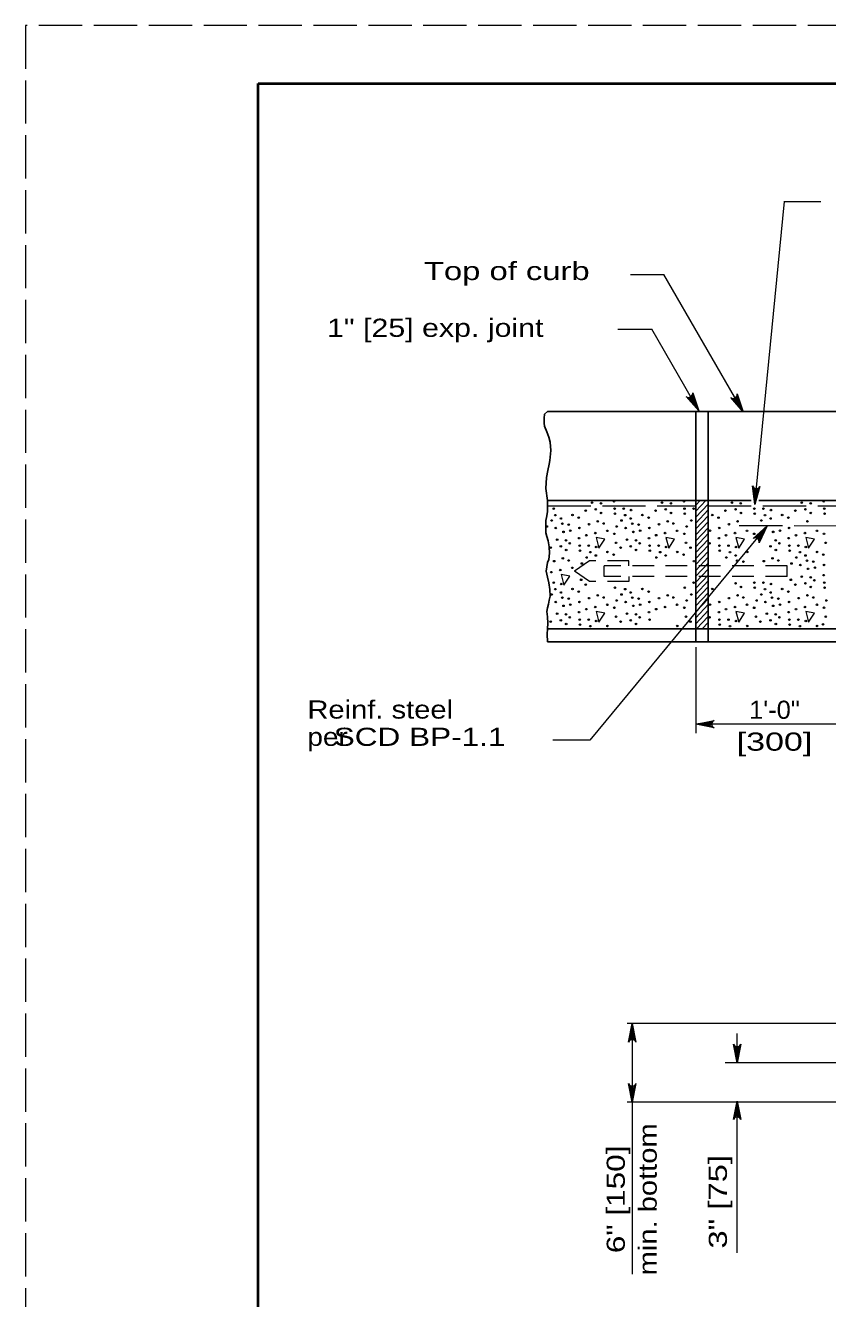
# Model space of a CAD drawing. Extents: x 1352.5 to 1386.5, y 735.9 to 779.9.
# Drawn here: x 1352.51 to 1359.41, y 768.97 to 779.92 of the extents above; entities that cross this region are included whole.
import ezdxf
from ezdxf.enums import TextEntityAlignment as Align

# ---------------------------------------------------------------- set-up
doc = ezdxf.new("R2010")
doc.units = 0
doc.header["$LTSCALE"] = 0.062
doc.linetypes.add('LONG_DASHED', pattern=[7.5, 6, -1.5])
doc.linetypes.add('MEDIUM_DASHED', pattern=[4.5, 3, -1.5])
doc.layers.add('1', color=7, linetype='Continuous', lineweight=13)

msp = doc.modelspace()

# ---------------------------------------------------------------- linework, layer by layer
at = {"layer": '1', "lineweight": 25}
for p, q in [((1354.513, 779.41967), (1386.013, 779.41967)), ((1356.99975, 776.599), (1369.78625, 776.599)), ((1358.27417, 776.599), (1358.27417, 774.62017)), ((1358.27417, 775.83442), (1356.99975, 775.83442)), ((1358.75225, 775.83442), (1358.38042, 775.83442)), ((1360.12208, 775.83442), (1358.818, 775.83442)), ((1358.38042, 774.62017), (1359.56983, 774.62017))]:
    msp.add_line(p, q, dxfattribs=at)
at = {"layer": '1'}
for p, q in [((1358.78142, 775.8), (1359.03875, 778.406)), ((1359.03108, 778.40683), (1359.34958, 778.40683)), ((1357.71275, 777.779), (1358.00133, 777.779)), ((1358.68267, 776.59883), (1358.00133, 777.779)), ((1357.60417, 777.307), (1357.89592, 777.307)), ((1358.30017, 776.60675), (1357.89592, 777.307)), ((1358.21083, 776.72175), (1358.30017, 776.60675)), ((1358.22192, 776.7225), (1358.30017, 776.60675)), ((1358.2315, 776.72625), (1358.30017, 776.60675)), ((1358.24142, 776.735), (1358.30017, 776.60675)), ((1358.24675, 776.74442), (1358.30017, 776.60675)), ((1358.59267, 776.71333), (1358.68267, 776.59883)), ((1358.60375, 776.71417), (1358.68267, 776.59883)), ((1358.61333, 776.718), (1358.68267, 776.59883)), ((1358.62317, 776.72675), (1358.68267, 776.59883)), ((1358.6285, 776.73617), (1358.68267, 776.59883)), ((1358.773, 775.94542), (1358.78142, 775.8)), ((1358.81542, 775.94367), (1358.78142, 775.8)), ((1358.7825, 775.93975), (1358.78142, 775.8)), ((1358.80567, 775.93892), (1358.78142, 775.8)), ((1358.79258, 775.93742), (1358.78142, 775.8)), ((1358.27417, 775.74275), (1358.36075, 775.83442)), ((1358.27417, 775.79367), (1358.31267, 775.83442)), ((1358.38042, 775.83442), (1358.27417, 775.83442)), ((1358.27417, 775.69192), (1358.38042, 775.80442)), ((1358.27417, 775.641), (1358.38042, 775.7535)), ((1358.27417, 775.59017), (1358.38042, 775.70258)), ((1358.27417, 775.53925), (1358.38042, 775.65167)), ((1358.27417, 775.48833), (1358.38042, 775.60083)), ((1358.7835, 775.5135), (1358.8895, 775.61617)), ((1358.79425, 775.51225), (1358.8895, 775.61617)), ((1358.80608, 775.50642), (1358.8895, 775.61617)), ((1358.81333, 775.49908), (1358.8895, 775.61617)), ((1358.81833, 775.48917), (1358.8895, 775.61617)), ((1358.27408, 775.43742), (1358.38042, 775.55)), ((1358.27417, 775.38658), (1358.38042, 775.49908)), ((1358.27417, 775.33575), (1358.38042, 775.44817)), ((1358.27417, 775.28483), (1358.38042, 775.39725)), ((1358.27417, 775.234), (1358.38042, 775.34642)), ((1358.27417, 775.18308), (1358.38042, 775.29558)), ((1358.27417, 775.13217), (1358.38042, 775.24467)), ((1358.27417, 775.08125), (1358.38042, 775.19383)), ((1358.27417, 775.0305), (1358.38042, 775.14292)), ((1358.27417, 774.97958), (1358.38042, 775.092)), ((1358.27417, 774.92867), (1358.38042, 775.04108)), ((1358.27417, 774.87775), (1358.38042, 774.99025)), ((1358.27417, 774.82692), (1358.38042, 774.93942)), ((1358.27417, 774.776), (1358.38042, 774.8885)), ((1358.28117, 774.73258), (1358.38042, 774.83758)), ((1358.32925, 774.73258), (1358.38042, 774.78667)), ((1358.37725, 774.73258), (1358.38042, 774.73583)), ((1358.27417, 774.57517), (1358.27417, 773.8335)), ((1358.41842, 773.93233), (1358.27417, 773.91217)), ((1358.4135, 773.92233), (1358.27417, 773.91217)), ((1358.412, 773.91217), (1358.27417, 773.91217)), ((1358.41458, 773.89917), (1358.27417, 773.91217)), ((1358.42008, 773.88983), (1358.27417, 773.91217)), ((1359.56983, 773.91217), (1358.27417, 773.91217)), ((1359.52733, 771.33708), (1357.68633, 771.33708)), ((1357.70658, 771.19108), (1357.72883, 771.33708)), ((1357.71592, 771.19667), (1357.72883, 771.33708)), ((1357.72883, 771.19917), (1357.72883, 771.33708)), ((1357.73908, 771.19767), (1357.72883, 771.33708)), ((1357.749, 771.19283), (1357.72883, 771.33708)), ((1357.72883, 771.33708), (1357.72883, 769.18275)), ((1358.63025, 771.00042), (1358.63025, 771.25167)), ((1358.61, 771.14467), (1358.63025, 771.00042)), ((1358.62, 771.13975), (1358.63025, 771.00042)), ((1358.6525, 771.14633), (1358.63025, 771.00042)), ((1358.64317, 771.14083), (1358.63025, 771.00042)), ((1358.63025, 771.13825), (1358.63025, 771.00042)), ((1363.12942, 771.00042), (1358.52633, 771.00042)), ((1357.70867, 770.80667), (1357.72883, 770.66242)), ((1357.71867, 770.80175), (1357.72883, 770.66242)), ((1357.75117, 770.80833), (1357.72883, 770.66242)), ((1357.74183, 770.80283), (1357.72883, 770.66242)), ((1357.72883, 770.80025), (1357.72883, 770.66242)), ((1359.52733, 770.66242), (1357.68633, 770.66242)), ((1358.60792, 770.52533), (1358.63025, 770.67125)), ((1358.61725, 770.53083), (1358.63025, 770.67125)), ((1358.63025, 770.53342), (1358.63025, 770.67125)), ((1358.64042, 770.53192), (1358.63025, 770.67125)), ((1358.65042, 770.527), (1358.63025, 770.67125)), ((1358.63025, 769.36675), (1358.63025, 770.67125))]:
    msp.add_line(p, q, dxfattribs=at)
at = {"layer": '1', "linetype": 'LONG_DASHED'}
for p, q in [((1356.99975, 775.7895), (1358.27417, 775.7895)), ((1358.38042, 775.7895), (1360.12208, 775.7895)), ((1358.64892, 775.61933), (1359.90083, 775.61817))]:
    msp.add_line(p, q, dxfattribs=at)
at = {"layer": '1', "linetype": 'MEDIUM_DASHED'}
for p, q in [((1357.48833, 775.18233), (1357.48833, 775.27225)), ((1359.06008, 775.27225), (1357.48833, 775.27225)), ((1359.06008, 775.18233), (1359.06008, 775.27225)), ((1357.36083, 775.13733), (1357.23217, 775.22733)), ((1357.70067, 775.13733), (1357.36083, 775.13733)), ((1359.06008, 775.18233), (1357.48833, 775.18233)), ((1357.70067, 775.18233), (1357.70067, 775.13733))]:
    msp.add_line(p, q, dxfattribs=at)
at = {"layer": '1', "linetype": 'LONG_DASHED'}
msp.add_lwpolyline([(1352.513, 757.91967), (1386.513, 757.91967), (1386.513, 779.91967), (1352.513, 779.91967)], close=True, dxfattribs=at)
at = {"layer": '1', "lineweight": 25}
for points in [[(1386.013, 758.41967), (1354.513, 758.41967), (1354.513, 779.41967)], [(1356.99975, 776.599), (1356.97533, 776.57875), (1356.97292, 776.54342), (1356.9705, 776.50042), (1356.97533, 776.47517), (1356.99442, 776.42467), (1357.01108, 776.37925), (1357.02308, 776.33625), (1357.02783, 776.26558), (1357.02067, 776.17967), (1357.01583, 776.14683), (1357.00392, 776.09383), (1356.99208, 776.03325), (1356.98725, 775.93725), (1356.99975, 775.83442)], [(1358.38042, 776.599), (1358.38042, 774.73258), (1358.38042, 774.62017)], [(1356.99975, 775.83442), (1356.99975, 775.7895), (1357.00158, 775.73767), (1356.99208, 775.68975), (1356.98725, 775.662), (1356.98725, 775.62917), (1356.98483, 775.58867), (1356.98483, 775.55583), (1356.99442, 775.52558), (1357.00633, 775.48767), (1357.01583, 775.43717), (1357.01825, 775.38167), (1357.01108, 775.32858), (1357.00158, 775.30075), (1356.98967, 775.2275), (1356.99925, 775.177), (1357.01108, 775.1265), (1357.02067, 775.07092), (1357.02308, 775.01283), (1357.01583, 774.9775), (1357.00867, 774.94467), (1356.99925, 774.91183), (1356.99442, 774.8815), (1357.00158, 774.83608), (1357.00392, 774.7805), (1356.99975, 774.73258), (1358.38042, 774.73258), (1359.56983, 774.73258)], [(1356.99975, 774.73258), (1356.99683, 774.6845), (1356.99975, 774.62017)], [(1358.38042, 774.62017), (1358.27417, 774.62017), (1356.99975, 774.62017)]]:
    msp.add_lwpolyline(points, dxfattribs=at)
at = {"layer": '1', "lineweight": 40}
msp.add_lwpolyline([(1354.513, 779.41967), (1386.013, 779.41967), (1386.013, 758.41967), (1354.513, 758.41967)], close=True, dxfattribs=at)
msp.add_lwpolyline([(1354.513, 779.41967), (1386.013, 779.41967), (1386.013, 758.41967), (1354.513, 758.41967)], close=True, dxfattribs=at)
at = {"layer": '1'}
for points in [[(1358.24842, 776.76075), (1358.30017, 776.60675), (1358.19317, 776.729)], [(1358.63, 776.75258), (1358.68267, 776.59883), (1358.575, 776.7205)], [(1358.82608, 775.95625), (1358.78142, 775.8), (1358.7625, 775.96142)], [(1358.8895, 775.61617), (1357.36375, 773.77533), (1357.04583, 773.77533)], [(1358.76775, 775.50858), (1358.8895, 775.61617), (1358.8185, 775.47008)], [(1358.4335, 773.88025), (1358.27417, 773.91217), (1358.4335, 773.944)], [(1357.697, 771.17775), (1357.72883, 771.33708), (1357.76075, 771.17775)], [(1358.66208, 771.15975), (1358.63025, 771.00042), (1358.59833, 771.15975)], [(1357.76075, 770.82175), (1357.72883, 770.66242), (1357.697, 770.82175)], [(1358.59833, 770.51192), (1358.63025, 770.67125), (1358.66208, 770.51192)]]:
    msp.add_lwpolyline(points, dxfattribs=at)
at = {"layer": '1', "lineweight": 25}
msp.add_lwpolyline([(1358.38042, 774.73258), (1358.38042, 775.83442), (1358.27417, 775.83442), (1358.27417, 774.73258)], close=True, dxfattribs=at)
at = {"layer": '1'}
for points in [[(1357.41808, 775.51725), (1357.44225, 775.425), (1357.49175, 775.50283)], [(1358.01883, 775.51725), (1358.04308, 775.425), (1358.0925, 775.50283)], [(1358.6195, 775.51725), (1358.64383, 775.425), (1358.69333, 775.50283)], [(1359.22025, 775.51725), (1359.24458, 775.425), (1359.29408, 775.50283)], [(1357.11767, 775.19917), (1357.14192, 775.107), (1357.19133, 775.18483)], [(1357.41808, 774.88117), (1357.44225, 774.789), (1357.49175, 774.86683)], [(1358.6195, 774.88117), (1358.64383, 774.789), (1358.69333, 774.86683)], [(1359.22025, 774.88117), (1359.24458, 774.789), (1359.29408, 774.86683)]]:
    msp.add_lwpolyline(points, close=True, dxfattribs=at)
at = {"layer": '1', "linetype": 'MEDIUM_DASHED'}
msp.add_lwpolyline([(1357.70067, 775.27225), (1357.70067, 775.31725), (1357.36083, 775.31725), (1357.23217, 775.22733)], dxfattribs=at)
at = {"layer": '1'}
for centre, start, end in [((1358.21434, 776.75603), 231.97282, 7.79895), ((1358.596, 776.74763), 232.30117, 8.1273), ((1358.7953, 775.97165), 197.46542, 333.29155), ((1358.78537, 775.47907), 344.86022, 120.68634), ((1358.44634, 773.91218), 112.08782, 247.91395), ((1357.72889, 771.16488), 22.08782, 157.91395), ((1358.63017, 771.17258), 202.08782, 337.91395), ((1357.72882, 770.83459), 202.08782, 337.91395), ((1358.63024, 770.49906), 22.08782, 157.91395)]:
    msp.add_arc(centre, 0.03438, start, end, dxfattribs=at)
for centre in [(1357.38373, 775.81688), (1357.46028, 775.81026), (1357.57247, 775.82886), (1357.98449, 775.81688), (1358.06104, 775.81026), (1358.17323, 775.82886), (1358.58525, 775.81688), (1358.6618, 775.81026), (1359.18601, 775.81688), (1359.26255, 775.81026), (1359.37475, 775.82886), (1357.05447, 775.76531), (1357.06744, 775.70865), (1357.11525, 775.6803), (1357.21502, 775.71035), (1357.26854, 775.68803), (1357.32862, 775.74814), (1357.41537, 775.75932), (1357.46108, 775.7281), (1357.57733, 775.76531), (1357.57973, 775.72153), (1357.65523, 775.76531), (1357.66819, 775.70865), (1357.716, 775.6803), (1357.71926, 775.75243), (1357.81578, 775.71035), (1357.8693, 775.68803), (1357.92937, 775.74814), (1358.01613, 775.75932), (1358.06184, 775.7281), (1358.17809, 775.76531), (1358.18049, 775.72153), (1358.25599, 775.76531), (1358.41654, 775.71035), (1358.47006, 775.68803), (1358.53013, 775.74814), (1358.61689, 775.75932), (1358.6626, 775.7281), (1358.77884, 775.76531), (1358.78125, 775.72153), (1358.85674, 775.76531), (1358.86971, 775.70865), (1358.91752, 775.6803), (1358.92077, 775.75243), (1359.0173, 775.71035), (1359.07081, 775.68803), (1359.13089, 775.74814), (1359.21765, 775.75932), (1359.26336, 775.7281), (1359.3796, 775.76531), (1359.38201, 775.72153), (1356.99494, 775.61134), (1357.03575, 775.66312), (1357.07144, 775.59788), (1357.12826, 775.63567), (1357.13792, 775.56523), (1357.18258, 775.62788), (1357.19635, 775.57556), (1357.27505, 775.59867), (1357.35805, 775.63111), (1357.4327, 775.65512), (1357.48216, 775.6371), (1357.51375, 775.5744), (1357.5957, 775.61134), (1357.6365, 775.66312), (1357.6722, 775.59788), (1357.72902, 775.63567), (1357.73868, 775.56523), (1357.78334, 775.62788), (1357.79711, 775.57556), (1357.87581, 775.59867), (1357.95881, 775.63111), (1358.03345, 775.65512), (1358.08292, 775.6371), (1358.11451, 775.5744), (1358.19646, 775.61134), (1358.23726, 775.66312), (1358.39786, 775.57556), (1358.47656, 775.59867), (1358.55957, 775.63111), (1358.63421, 775.65512), (1358.71526, 775.5744), (1358.83802, 775.66312), (1358.9402, 775.56523), (1358.99862, 775.57556), (1359.07732, 775.59867), (1359.23497, 775.65512), (1359.31602, 775.5744), (1357.08336, 775.49887), (1357.1599, 775.49224), (1357.19179, 775.46707), (1357.27209, 775.51085), (1357.27695, 775.4473), (1357.33367, 775.53661), (1357.35485, 775.4473), (1357.41077, 775.55463), (1357.57543, 775.54864), (1357.59004, 775.47136), (1357.68411, 775.49887), (1357.76066, 775.49224), (1357.79255, 775.46707), (1357.87285, 775.51085), (1357.87771, 775.4473), (1357.93443, 775.53661), (1357.95561, 775.4473), (1358.01153, 775.55463), (1358.17618, 775.54864), (1358.1908, 775.47136), (1358.39331, 775.46707), (1358.47361, 775.51085), (1358.47847, 775.4473), (1358.53519, 775.53661), (1358.55636, 775.4473), (1358.61228, 775.55463), (1358.77694, 775.54864), (1358.96218, 775.49224), (1358.99407, 775.46707), (1359.07437, 775.51085), (1359.07922, 775.4473), (1359.13595, 775.53661), (1359.15712, 775.4473), (1359.21304, 775.55463), (1359.3777, 775.54864), (1359.39232, 775.47136), (1357.02824, 775.43012), (1357.115, 775.44131), (1357.13232, 775.33711), (1357.1607, 775.41009), (1357.27935, 775.40352), (1357.33612, 775.34511), (1357.36781, 775.39064), (1357.41562, 775.36228), (1357.41888, 775.43442), (1357.5154, 775.39233), (1357.56892, 775.37002), (1357.62899, 775.43012), (1357.71575, 775.44131), (1357.76146, 775.41009), (1357.88011, 775.40352), (1357.93688, 775.34511), (1357.96857, 775.39064), (1358.01638, 775.36228), (1358.01964, 775.43442), (1358.11616, 775.39233), (1358.16968, 775.37002), (1358.22975, 775.43012), (1358.48087, 775.40352), (1358.53764, 775.34511), (1358.56933, 775.39064), (1358.61714, 775.36228), (1358.62039, 775.43442), (1358.71692, 775.39233), (1358.91727, 775.44131), (1358.93459, 775.33711), (1358.96298, 775.41009), (1359.08163, 775.40352), (1359.1384, 775.34511), (1359.17009, 775.39064), (1359.2179, 775.36228), (1359.22115, 775.43442), (1359.31767, 775.39233), (1359.37119, 775.37002), (1357.05767, 775.3131), (1357.11039, 775.23661), (1357.18178, 775.31908), (1357.21337, 775.25638), (1357.29532, 775.29333), (1358.25919, 775.3131), (1358.63016, 775.31765), (1358.68448, 775.30986), (1358.85995, 775.3131), (1358.98405, 775.31908), (1359.0976, 775.29333), (1359.17409, 775.27986), (1359.23091, 775.31765), (1359.24058, 775.24721), (1359.28523, 775.30986), (1359.299, 775.25755), (1359.3777, 775.28066), (1357.03329, 775.21859), (1357.05447, 775.12928), (1357.28967, 775.15335), (1358.25599, 775.12928), (1358.61689, 775.12329), (1358.77884, 775.12928), (1358.85674, 775.12928), (1359.09194, 775.15335), (1359.18601, 775.18085), (1359.21765, 775.12329), (1359.26255, 775.17423), (1359.29445, 775.14905), (1359.37475, 775.19283), (1359.3796, 775.12928), (1357.03575, 775.02709), (1357.06744, 775.07262), (1357.11525, 775.04427), (1357.1185, 775.1164), (1357.21502, 775.07432), (1357.26854, 775.05201), (1357.32862, 775.11211), (1357.4327, 775.01909), (1357.57973, 775.0855), (1357.6365, 775.02709), (1357.66819, 775.07262), (1357.716, 775.04427), (1357.81578, 775.07432), (1357.8693, 775.05201), (1358.03345, 775.01909), (1358.18049, 775.0855), (1358.23726, 775.02709), (1358.41654, 775.07432), (1358.63421, 775.01909), (1358.6626, 775.09208), (1358.78125, 775.0855), (1358.83802, 775.02709), (1358.86971, 775.07262), (1358.91752, 775.04427), (1358.92077, 775.1164), (1359.0173, 775.07432), (1359.07081, 775.05201), (1359.13089, 775.11211), (1359.23497, 775.01909), (1359.26336, 775.09208), (1359.38201, 775.0855), (1357.07144, 774.96185), (1357.12826, 774.99964), (1357.13792, 774.9292), (1357.18258, 774.99185), (1357.19635, 774.93953), (1357.27505, 774.96264), (1357.33367, 774.90058), (1357.35805, 774.99508), (1357.41077, 774.9186), (1357.48216, 775.00107), (1357.51375, 774.93837), (1357.57543, 774.91261), (1357.5957, 774.97531), (1357.6722, 774.96185), (1357.72902, 774.99964), (1357.73868, 774.9292), (1357.78334, 774.99185), (1357.79711, 774.93953), (1357.87581, 774.96264), (1357.93443, 774.90058), (1357.95881, 774.99508), (1358.01153, 774.9186), (1358.08292, 775.00107), (1358.11451, 774.93837), (1358.17618, 774.91261), (1358.19646, 774.97531), (1358.39786, 774.93953), (1358.47656, 774.96264), (1358.53519, 774.90058), (1358.55957, 774.99508), (1358.61228, 774.9186), (1358.68367, 775.00107), (1358.71526, 774.93837), (1358.77694, 774.91261), (1358.79722, 774.97531), (1358.87371, 774.96185), (1358.93054, 774.99964), (1358.9402, 774.9292), (1358.98485, 774.99185), (1358.99862, 774.93953), (1359.07732, 774.96264), (1359.13595, 774.90058), (1359.16033, 774.99508), (1359.21304, 774.9186), (1359.28443, 775.00107), (1359.31602, 774.93837), (1359.3777, 774.91261), (1359.39798, 774.97531), (1357.02824, 774.7941), (1357.08336, 774.86284), (1357.115, 774.80528), (1357.1599, 774.85621), (1357.19179, 774.83104), (1357.27209, 774.87482), (1357.27695, 774.81127), (1357.35485, 774.81127), (1357.41888, 774.79839), (1357.59004, 774.83533), (1357.62899, 774.7941), (1357.68411, 774.86284), (1357.71575, 774.80528), (1357.76066, 774.85621), (1357.79255, 774.83104), (1357.87285, 774.87482), (1357.87771, 774.81127), (1358.1908, 774.83533), (1358.22975, 774.7941), (1358.39331, 774.83104), (1358.47361, 774.87482), (1358.47847, 774.81127), (1358.55636, 774.81127), (1358.62039, 774.79839), (1358.79156, 774.83533), (1358.83051, 774.7941), (1358.88563, 774.86284), (1358.91727, 774.80528), (1358.96218, 774.85621), (1358.99407, 774.83104), (1359.07437, 774.87482), (1359.07922, 774.81127), (1359.15712, 774.81127), (1359.22115, 774.79839), (1359.39232, 774.83533), (1357.1607, 774.77406), (1357.27935, 774.76749), (1357.36781, 774.75461), (1357.5154, 774.7563), (1357.76146, 774.77406), (1358.11616, 774.7563), (1358.48087, 774.76749), (1358.56933, 774.75461), (1358.71692, 774.7563), (1358.96298, 774.77406), (1359.08163, 774.76749), (1359.17009, 774.75461), (1359.31767, 774.7563), (1359.3681, 774.76957)]:
    msp.add_ellipse(centre, major_axis=(0, 0.0068), ratio=0.944544, dxfattribs=at)

# ---------------------------------------------------------------- texts
for s, width, p in [('Top of curb', 1.35, (1355.93817, 777.73042)), ('1" [25] exp. joint', 1.25, (1355.10467, 777.24208)), ('Reinf. steel', 1.2, (1354.9365, 773.95975)), ('per', 1.15, (1354.9365, 773.72508)), ('   SCD BP-1.1', 1.3, (1354.9365, 773.72508))]:
    msp.add_text(s, height=0.156, dxfattribs=dict(at, width=width)).set_placement(p)
for s, width, p in [('1\'-0"', 1.05, (1358.95154, 773.95775)), ('[300]', 1.4, (1358.95158, 773.68375))]:
    msp.add_text(s, height=0.156, dxfattribs=dict(at, width=width)).set_placement(p, align=Align.CENTER)
for s, width, p in [('min. bottom', 1.2, (1357.93908, 769.82596)), ('6" [150]', 1.3, (1357.66508, 769.826))]:
    msp.add_text(s, height=0.156, rotation=90, dxfattribs=dict(at, width=width)).set_placement(p, align=Align.CENTER)
at = {"layer": '1', "width": 1.35}
msp.add_text('3" [75]', height=0.156, rotation=90, dxfattribs=at).set_placement((1358.54258, 769.40275))

doc.saveas('drawing.dxf')
